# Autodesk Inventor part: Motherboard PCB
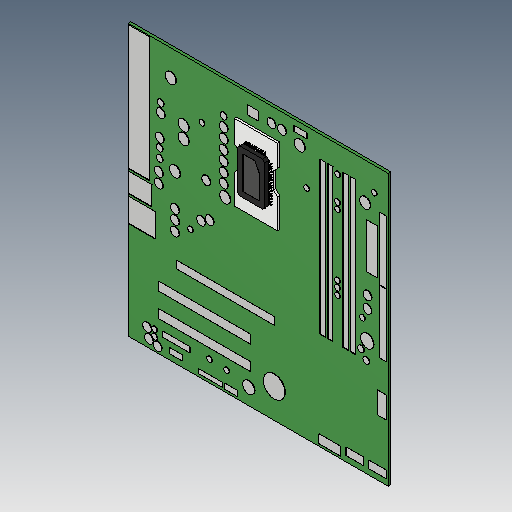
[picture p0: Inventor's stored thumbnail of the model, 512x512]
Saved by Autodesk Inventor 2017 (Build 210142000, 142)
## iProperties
Created: 2005-11
Part Number: Motherboard PCB
Material: Generic
Document SubType Name: Modeling
Designer: DanielSeverino
Density: 1 g/cm^3
Appearance: Default
Author: DanielSeverino
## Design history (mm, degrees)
feature "Solid1"
body "Solid2"
